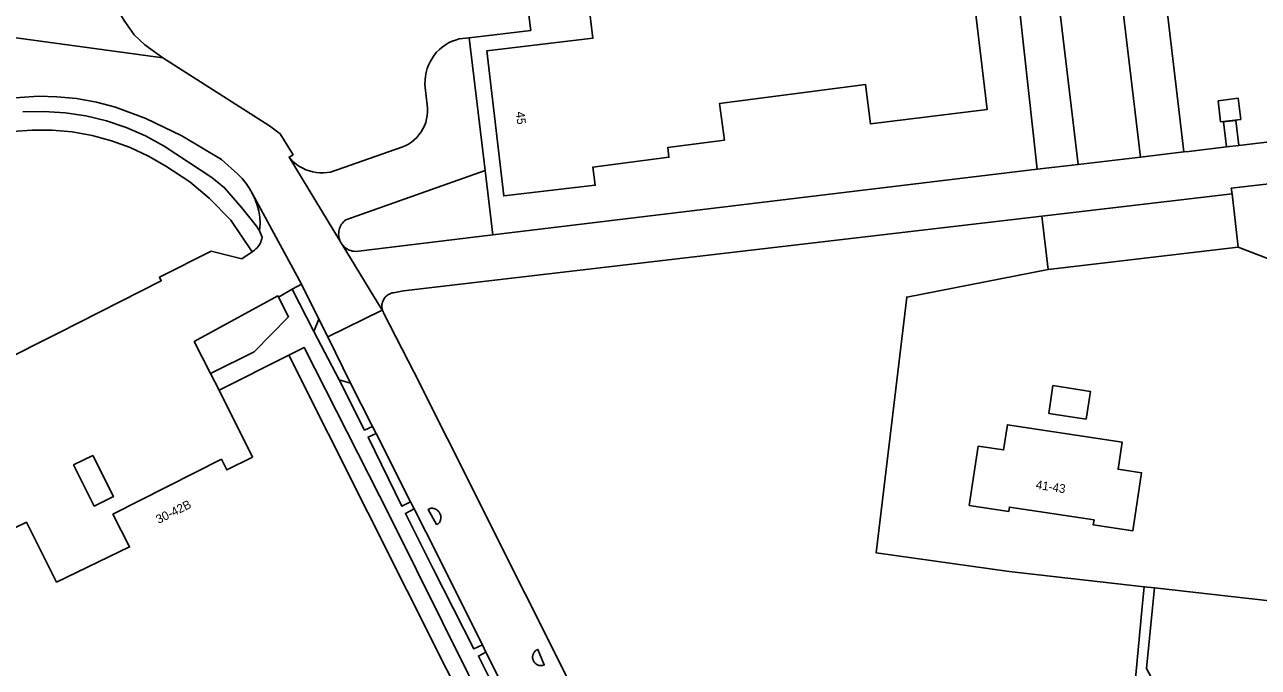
# Model space of a CAD drawing. Extents: x 158132 to 159664, y 385256 to 387218.
# Drawn here: x 159028.7 to 159170.4, y 386531.1 to 386604.9 of the extents above; entities that cross this region are included whole.
import ezdxf

# ---------------------------------------------------------------- set-up
doc = ezdxf.new("R2010")
doc.units = 0
for name, color, linetype in [('IMGEO_Berm_groen', 7, 'Continuous'), ('IMGEO_Erf', 7, 'Continuous'), ('IMGEO_Groenvoorziening', 7, 'Continuous'), ('IMGEO_Loofbos', 7, 'Continuous'), ('IMGEO_Pand', 7, 'Continuous'), ('IMGEO_Pand_nummerreeks', 7, 'Continuous'), ('IMGEO_Parkeervlak_gesloten', 7, 'Continuous'), ('IMGEO_Parkeervlak_open', 7, 'Continuous'), ('IMGEO_Rijbaan_lokaal_gesloten', 7, 'Continuous'), ('IMGEO_Rijbaan_lokaal_open', 7, 'Continuous'), ('IMGEO_Verkeerseiland_gesloten', 7, 'Continuous'), ('IMGEO_Voetpad_open', 7, 'Continuous')]:
    doc.layers.add(name, color=color, linetype=linetype)

msp = doc.modelspace()

# ---------------------------------------------------------------- linework, layer by layer
at = {"layer": 'IMGEO_Berm_groen'}
msp.add_lwpolyline([(159028.48, 386594.92), (159030.9, 386594.98), (159033.32, 386594.83), (159035.71, 386594.47), (159038.07, 386593.9), (159040.36, 386593.13), (159042.58, 386592.16), (159044.71, 386591), (159050.19, 386587.39), (159051.65, 386586.21), (159053.63, 386583.89), (159055.32, 386581.82), (159055.67, 386581.25), (159055.74, 386582.11), (159055.68, 386582.82), (159055.57, 386583.51), (159055.39, 386584.2), (159055.15, 386584.87), (159054.86, 386585.51), (159054.52, 386586.13), (159054.12, 386586.72), (159053.68, 386587.27), (159053.19, 386587.78), (159051.31, 386589.44), (159046.74, 386592.18), (159042.61, 386594.15), (159039.13, 386595.45), (159036.92, 386596.06), (159034.65, 386596.46), (159032.37, 386596.65), (159030.29, 386596.74), (159024.92, 386596.33)], dxfattribs=at)
for points in [[(159060.48, 386575.13), (159059.42, 386574.58), (159061.91, 386569.71), (159062.46, 386571.11)], [(159059, 386571.4), (159057.85, 386573.66), (159057.77, 386573.8), (159048.17, 386568.54), (159050.03, 386564.89), (159055.03, 386567.36)], [(159066.12, 386563.76), (159064.8, 386564.17), (159067.73, 386558.38), (159068.64, 386558.78)], [(159069.05, 386557.98), (159068.14, 386557.58), (159072.03, 386549.64), (159073.01, 386550.16)], [(159074.81, 386546.61), (159073.43, 386549.34), (159072.43, 386548.81), (159075.6, 386542.45), (159080.3, 386533.25), (159081.26, 386533.72)], [(159083.47, 386529.31), (159081.68, 386532.89), (159080.81, 386532.42), (159089.95, 386514.21), (159090.83, 386514.64)]]:
    msp.add_lwpolyline(points, close=True, dxfattribs=at)
at = {"layer": 'IMGEO_Erf'}
for points in [[(159168.09, 386579.39), (159146.27, 386576.84), (159130.01, 386573.65), (159126.49, 386544.29), (159141.76, 386542.14), (159157.3, 386540.4), (159158.49, 386540.26), (159174.04, 386538.52), (159176.11, 386538.29), (159179.55, 386575)], [(159151.11, 386562.83), (159150.62, 386559.65), (159146.32, 386560.3), (159146.81, 386563.49)], [(159155.97, 386546.81), (159151.44, 386547.5), (159151.53, 386548.07), (159141.81, 386549.55), (159141.73, 386549.04), (159137.19, 386549.73), (159138.23, 386556.55), (159141.13, 386556.11), (159141.57, 386559), (159154.77, 386556.99), (159154.3, 386553.89), (159156.99, 386553.48)]]:
    msp.add_lwpolyline(points, close=True, dxfattribs=at)
at = {"layer": 'IMGEO_Groenvoorziening'}
for points in [[(159157.64, 386625.98), (159161.85, 386590.32), (159162.42, 386590.39), (159166.74, 386590.91), (159166.39, 386593.77), (159167.8, 386593.95), (159168.15, 386591.07), (159175.18, 386591.91)], [(159040.19, 386605.29), (159041.26, 386603.78), (159042.49, 386602.63), (159044.57, 386601.15), (159056.81, 386593.34), (159058.02, 386592.39), (159059.51, 386590.01), (159059.05, 386589.73), (159059.32, 386589.42), (159059.62, 386589.14), (159059.93, 386588.88), (159060.27, 386588.65), (159060.63, 386588.45), (159061, 386588.28), (159061.39, 386588.14), (159061.79, 386588.03), (159062.19, 386587.96), (159062.6, 386587.92), (159063.01, 386587.92), (159063.42, 386587.95), (159063.82, 386588.02), (159072.03, 386590.86), (159072.41, 386591.02), (159072.77, 386591.22), (159073.11, 386591.44), (159073.42, 386591.7), (159073.72, 386591.98), (159073.98, 386592.29), (159074.22, 386592.62), (159074.43, 386592.97), (159074.61, 386593.34), (159074.75, 386593.72), (159074.85, 386594.11), (159074.92, 386594.51), (159074.96, 386594.92), (159074.96, 386595.33), (159074.92, 386595.73), (159074.7, 386597.72), (159074.67, 386598.16), (159074.68, 386598.6), (159074.72, 386599.03), (159074.8, 386599.46), (159074.92, 386599.89), (159075.07, 386600.3), (159075.26, 386600.69), (159075.48, 386601.07), (159075.73, 386601.43), (159076.01, 386601.77), (159076.32, 386602.08), (159076.65, 386602.36), (159077.01, 386602.62), (159077.38, 386602.84), (159077.78, 386603.03), (159078.19, 386603.18), (159078.61, 386603.31), (159079.74, 386603.44), (159086.82, 386604.28), (159086.76, 386604.82), (159086.16, 386609.81)], [(159025.65, 386566.07), (159032.6, 386569.55), (159044.38, 386575.53), (159044.19, 386575.96), (159050.09, 386578.94), (159053.63, 386578.06), (159054.82, 386578.85), (159052.35, 386582.48), (159049.86, 386585.02), (159047.64, 386586.89), (159044.91, 386588.71), (159042.91, 386589.86), (159040.82, 386590.83), (159038.65, 386591.62), (159036.42, 386592.22), (159034.14, 386592.62), (159031.85, 386592.83), (159029.54, 386592.84), (159027.24, 386592.66)], [(159146.27, 386576.84), (159145.55, 386582.95), (159072.19, 386574.38), (159071.06, 386574.16), (159070.92, 386574.14), (159070.79, 386574.1), (159070.66, 386574.05), (159070.54, 386573.99), (159070.42, 386573.92), (159070.31, 386573.84), (159070.21, 386573.75), (159070.11, 386573.65), (159070.03, 386573.55), (159069.95, 386573.43), (159069.89, 386573.31), (159069.83, 386573.19), (159069.79, 386573.06), (159069.75, 386572.93), (159069.73, 386572.79), (159069.72, 386572.65), (159069.73, 386572.52), (159069.74, 386572.38), (159069.77, 386572.25), (159069.8, 386572.11), (159069.86, 386571.99), (159069.92, 386571.86), (159073.41, 386564.98), (159077.26, 386557.36), (159086.18, 386539.58), (159101.17, 386509.73)], [(159148.23, 386529.21), (159156.1, 386528.28), (159156.17, 386528.64), (159157.04, 386538.09), (159157.3, 386540.4), (159141.76, 386542.14), (159126.49, 386544.29), (159130.01, 386573.65), (159146.27, 386576.84)]]:
    msp.add_lwpolyline(points, dxfattribs=at)
for points in [[(159168.1, 386596.5), (159168.38, 386594.06), (159166.07, 386593.77), (159165.79, 386596.21)], [(159081.58, 386588.19), (159065.57, 386582.53), (159065.44, 386582.42), (159065.31, 386582.3), (159065.19, 386582.16), (159065.09, 386582.02), (159065, 386581.87), (159064.92, 386581.71), (159064.86, 386581.55), (159064.81, 386581.38), (159064.77, 386581.21), (159064.76, 386581.03), (159064.75, 386580.85), (159064.77, 386580.68), (159064.79, 386580.51), (159064.84, 386580.33), (159064.89, 386580.17), (159064.97, 386580.01), (159065.05, 386579.85), (159065.15, 386579.71), (159065.26, 386579.57), (159065.39, 386579.44), (159065.52, 386579.33), (159065.66, 386579.23), (159065.82, 386579.14), (159065.97, 386579.06), (159066.14, 386579), (159066.31, 386578.95), (159066.48, 386578.92), (159066.71, 386578.91), (159082.47, 386580.81)], [(159070.67, 386548.43), (159060.8, 386567.86), (159059.03, 386566.97), (159086.21, 386512.87), (159088, 386513.77), (159082.68, 386524.24)]]:
    msp.add_lwpolyline(points, close=True, dxfattribs=at)
at = {"layer": 'IMGEO_Loofbos'}
msp.add_lwpolyline([(159250.17, 386500), (159194.12, 386589.79), (159192.73, 386592.19), (159192.21, 386592.03), (159176.64, 386587.24), (159167.3, 386586.15), (159167.38, 386585.5), (159168.09, 386579.39), (159179.55, 386575), (159176.11, 386538.29), (159174.04, 386538.52), (159158.49, 386540.26), (159158.23, 386537.96), (159157.57, 386530.99)], dxfattribs=at)
at = {"layer": 'IMGEO_Pand'}
for points in [[(159083.72, 386585.27), (159094.23, 386586.5), (159093.96, 386588.58), (159102.69, 386589.71), (159102.55, 386590.83), (159109.06, 386591.67), (159108.52, 386595.89), (159125.29, 386598.06), (159125.84, 386593.54), (159139.27, 386595.21), (159136.34, 386619.6), (159122.39, 386617.92), (159122.93, 386613.74), (159106.38, 386611.59), (159106.64, 386609.58), (159093.42, 386607.87), (159093.96, 386603.38), (159081.77, 386601.93)], [(159168.1, 386596.5), (159165.79, 386596.21), (159166.07, 386593.77), (159168.38, 386594.06)], [(159150.62, 386559.65), (159151.11, 386562.83), (159146.81, 386563.49), (159146.32, 386560.3)], [(159155.97, 386546.81), (159156.99, 386553.48), (159154.3, 386553.89), (159154.77, 386556.99), (159141.57, 386559), (159141.13, 386556.11), (159138.23, 386556.55), (159137.19, 386549.73), (159141.73, 386549.04), (159141.81, 386549.55), (159151.53, 386548.07), (159151.44, 386547.5)]]:
    msp.add_lwpolyline(points, close=True, dxfattribs=at)
msp.add_lwpolyline([(159086.21, 386512.87), (159059.03, 386566.97), (159051.01, 386562.95), (159054.86, 386555.28), (159051.91, 386553.8), (159051.29, 386555.03), (159038.83, 386548.71), (159040.73, 386544.97), (159032.36, 386540.93), (159028.89, 386547.79), (159026.2, 386546.5), (159024.99, 386548.9), (159009.85, 386541.29), (159011.17, 386538.61), (159005.81, 386535.92), (159008.38, 386530.8)], dxfattribs=at)
at = {"layer": 'IMGEO_Parkeervlak_gesloten'}
msp.add_lwpolyline([(159034.3, 386554.39), (159036.68, 386549.66), (159038.88, 386550.74), (159036.5, 386555.47)], close=True, dxfattribs=at)
at = {"layer": 'IMGEO_Parkeervlak_open'}
for points in [[(159157.64, 386625.98), (159152.62, 386625.38), (159156.87, 386589.74), (159161.85, 386590.32)], [(159145.47, 386624.52), (159141.03, 386623.99), (159141.5, 386620.01), (159144.99, 386588.33), (159149.71, 386588.89)], [(159063.5, 386569.1), (159062.46, 386571.11), (159061.91, 386569.71), (159064.8, 386564.17), (159066.12, 386563.76)], [(159034.3, 386554.39), (159036.5, 386555.47), (159038.88, 386550.74), (159036.68, 386549.66)]]:
    msp.add_lwpolyline(points, close=True, dxfattribs=at)
for points in [[(159051.01, 386562.95), (159050.03, 386564.89), (159048.17, 386568.54), (159057.77, 386573.8), (159057.85, 386573.66), (159059.42, 386574.58), (159060.48, 386575.13), (159054.86, 386585.51), (159055.15, 386584.87), (159055.39, 386584.2), (159055.57, 386583.51), (159055.68, 386582.82), (159055.74, 386582.11), (159055.67, 386581.25), (159055.96, 386580.55), (159055.93, 386580.35), (159055.87, 386580.16), (159055.8, 386579.98), (159055.72, 386579.8), (159055.62, 386579.63), (159055.51, 386579.47), (159055.38, 386579.32), (159055.24, 386579.18), (159055.09, 386579.05), (159054.93, 386578.93), (159054.82, 386578.85), (159053.63, 386578.06), (159050.09, 386578.94), (159044.19, 386575.96), (159044.38, 386575.53), (159032.6, 386569.55), (159025.65, 386566.07)], [(159008.94, 386543.13), (159009.85, 386541.29), (159024.99, 386548.9), (159026.2, 386546.5), (159028.89, 386547.79), (159032.36, 386540.93), (159040.73, 386544.97), (159038.83, 386548.71), (159051.29, 386555.03), (159051.91, 386553.8), (159054.86, 386555.28), (159051.01, 386562.95)]]:
    msp.add_lwpolyline(points, dxfattribs=at)
at = {"layer": 'IMGEO_Rijbaan_lokaal_gesloten'}
for points in [[(159023.71, 386603.96), (159044.57, 386601.15), (159042.49, 386602.63), (159041.26, 386603.78), (159040.19, 386605.29), (159039.36, 386606.65), (159038.66, 386608.33), (159037.97, 386610.71)], [(159024.92, 386596.33), (159030.29, 386596.74), (159032.37, 386596.65), (159034.65, 386596.46), (159036.92, 386596.06), (159039.13, 386595.45), (159042.61, 386594.15), (159046.74, 386592.18), (159051.31, 386589.44), (159053.19, 386587.78), (159053.68, 386587.27), (159054.12, 386586.72), (159054.52, 386586.13), (159054.86, 386585.51), (159060.48, 386575.13), (159062.46, 386571.11), (159063.5, 386569.1), (159069.76, 386572.15), (159065.15, 386579.71), (159065.05, 386579.85), (159064.97, 386580.01), (159059.05, 386589.73), (159059.51, 386590.01), (159058.02, 386592.39), (159056.81, 386593.34), (159044.57, 386601.15), (159023.71, 386603.96)]]:
    msp.add_lwpolyline(points, dxfattribs=at)
at = {"layer": 'IMGEO_Rijbaan_lokaal_open'}
for points in [[(159152.62, 386625.38), (159145.47, 386624.52), (159149.71, 386588.89), (159156.87, 386589.74)], [(159167.38, 386585.5), (159145.55, 386582.95), (159146.27, 386576.84), (159168.09, 386579.39)], [(159075.03, 386549.25), (159075.27, 386549.38), (159075.36, 386549.4), (159075.45, 386549.4), (159075.54, 386549.4), (159075.63, 386549.39), (159075.71, 386549.37), (159075.8, 386549.34), (159075.88, 386549.31), (159075.96, 386549.27), (159076.04, 386549.22), (159076.11, 386549.16), (159076.18, 386549.1), (159076.24, 386549.04), (159076.3, 386548.96), (159076.35, 386548.89), (159076.39, 386548.81), (159076.43, 386548.73), (159076.46, 386548.64), (159076.48, 386548.55), (159076.49, 386548.46), (159076.49, 386548.37), (159076.49, 386548.28), (159076.48, 386548.19), (159076.46, 386548.1), (159076.44, 386548.02), (159076.4, 386547.93), (159076.36, 386547.85), (159076.32, 386547.77), (159076.26, 386547.7), (159076.2, 386547.63), (159076.01, 386547.55)], [(159088.1, 386531.33), (159088.02, 386531.33), (159087.93, 386531.34), (159087.85, 386531.35), (159087.76, 386531.36), (159087.68, 386531.39), (159087.61, 386531.42), (159087.53, 386531.46), (159087.46, 386531.51), (159087.39, 386531.56), (159087.33, 386531.61), (159087.27, 386531.68), (159087.22, 386531.74), (159087.17, 386531.81), (159087.13, 386531.89), (159087.1, 386531.97), (159087.07, 386532.05), (159087.05, 386532.13), (159087.04, 386532.21), (159087.04, 386532.3), (159087.04, 386532.38), (159087.05, 386532.47), (159087.06, 386532.55), (159087.09, 386532.63), (159087.12, 386532.71), (159087.15, 386532.78), (159087.2, 386532.86), (159087.25, 386532.92), (159087.3, 386532.99), (159087.36, 386533.05), (159087.43, 386533.1), (159087.64, 386533.19), (159088.38, 386531.41), (159088.18, 386531.35)]]:
    msp.add_lwpolyline(points, close=True, dxfattribs=at)
for points in [[(159175.18, 386591.91), (159168.15, 386591.07), (159166.74, 386590.91), (159162.42, 386590.39), (159161.85, 386590.32), (159156.87, 386589.74), (159149.71, 386588.89), (159144.99, 386588.33), (159082.47, 386580.81), (159066.71, 386578.91), (159066.48, 386578.92), (159066.31, 386578.95), (159066.14, 386579), (159065.97, 386579.06), (159065.82, 386579.14), (159065.66, 386579.23), (159065.52, 386579.33), (159065.39, 386579.44), (159065.26, 386579.57), (159065.15, 386579.71), (159069.76, 386572.15), (159069.86, 386571.99), (159069.8, 386572.11), (159069.77, 386572.25), (159069.74, 386572.38), (159069.73, 386572.52), (159069.72, 386572.65), (159069.73, 386572.79), (159069.75, 386572.93), (159069.79, 386573.06), (159069.83, 386573.19), (159069.89, 386573.31), (159069.95, 386573.43), (159070.03, 386573.55), (159070.11, 386573.65), (159070.21, 386573.75), (159070.31, 386573.84), (159070.42, 386573.92), (159070.54, 386573.99), (159070.66, 386574.05), (159070.79, 386574.1), (159070.92, 386574.14), (159071.06, 386574.16), (159072.19, 386574.38), (159145.55, 386582.95), (159167.38, 386585.5), (159167.3, 386586.15), (159176.64, 386587.24)], [(159101.17, 386509.73), (159086.18, 386539.58), (159077.26, 386557.36), (159073.41, 386564.98), (159069.92, 386571.86), (159069.86, 386571.99), (159069.76, 386572.15), (159063.5, 386569.1), (159066.12, 386563.76), (159068.64, 386558.78), (159069.05, 386557.98), (159073.01, 386550.16), (159073.43, 386549.34), (159074.81, 386546.61), (159081.26, 386533.72), (159081.68, 386532.89), (159083.47, 386529.31)]]:
    msp.add_lwpolyline(points, dxfattribs=at)
at = {"layer": 'IMGEO_Verkeerseiland_gesloten'}
for points in [[(159075.27, 386549.38), (159075.03, 386549.25), (159076.01, 386547.55), (159076.2, 386547.63), (159076.26, 386547.7), (159076.32, 386547.77), (159076.36, 386547.85), (159076.4, 386547.93), (159076.44, 386548.02), (159076.46, 386548.1), (159076.48, 386548.19), (159076.49, 386548.28), (159076.49, 386548.37), (159076.49, 386548.46), (159076.48, 386548.55), (159076.46, 386548.64), (159076.43, 386548.73), (159076.39, 386548.81), (159076.35, 386548.89), (159076.3, 386548.96), (159076.24, 386549.04), (159076.18, 386549.1), (159076.11, 386549.16), (159076.04, 386549.22), (159075.96, 386549.27), (159075.88, 386549.31), (159075.8, 386549.34), (159075.71, 386549.37), (159075.63, 386549.39), (159075.54, 386549.4), (159075.45, 386549.4), (159075.36, 386549.4)], [(159088.18, 386531.35), (159088.38, 386531.41), (159087.64, 386533.19), (159087.43, 386533.1), (159087.36, 386533.05), (159087.3, 386532.99), (159087.25, 386532.92), (159087.2, 386532.86), (159087.15, 386532.78), (159087.12, 386532.71), (159087.09, 386532.63), (159087.06, 386532.55), (159087.05, 386532.47), (159087.04, 386532.38), (159087.04, 386532.3), (159087.04, 386532.21), (159087.05, 386532.13), (159087.07, 386532.05), (159087.1, 386531.97), (159087.13, 386531.89), (159087.17, 386531.81), (159087.22, 386531.74), (159087.27, 386531.68), (159087.33, 386531.61), (159087.39, 386531.56), (159087.46, 386531.51), (159087.53, 386531.46), (159087.61, 386531.42), (159087.68, 386531.39), (159087.76, 386531.36), (159087.85, 386531.35), (159087.93, 386531.34), (159088.02, 386531.33), (159088.1, 386531.33)]]:
    msp.add_lwpolyline(points, close=True, dxfattribs=at)
at = {"layer": 'IMGEO_Voetpad_open'}
for points in [[(159138.19, 386623.65), (159121.25, 386621.63), (159120.92, 386624.39), (159105.07, 386622.5), (159105.83, 386616.14), (159094.16, 386614.74), (159092.39, 386614.53), (159092.86, 386610.61), (159086.16, 386609.81), (159086.76, 386604.82), (159086.82, 386604.28), (159079.74, 386603.44), (159081.58, 386588.19), (159082.47, 386580.81), (159144.99, 386588.33), (159141.5, 386620.01), (159138.66, 386619.69)], [(159106.64, 386609.58), (159106.38, 386611.59), (159122.93, 386613.74), (159122.39, 386617.92), (159136.34, 386619.6), (159139.27, 386595.21), (159125.84, 386593.54), (159125.29, 386598.06), (159108.52, 386595.89), (159109.06, 386591.67), (159102.55, 386590.83), (159102.69, 386589.71), (159093.96, 386588.58), (159094.23, 386586.5), (159083.72, 386585.27), (159081.77, 386601.93), (159093.96, 386603.38), (159093.42, 386607.87)], [(159081.58, 386588.19), (159079.74, 386603.44), (159078.61, 386603.31), (159078.19, 386603.18), (159077.78, 386603.03), (159077.38, 386602.84), (159077.01, 386602.62), (159076.65, 386602.36), (159076.32, 386602.08), (159076.01, 386601.77), (159075.73, 386601.43), (159075.48, 386601.07), (159075.26, 386600.69), (159075.07, 386600.3), (159074.92, 386599.89), (159074.8, 386599.46), (159074.72, 386599.03), (159074.68, 386598.6), (159074.67, 386598.16), (159074.7, 386597.72), (159074.92, 386595.73), (159074.96, 386595.33), (159074.96, 386594.92), (159074.92, 386594.51), (159074.85, 386594.11), (159074.75, 386593.72), (159074.61, 386593.34), (159074.43, 386592.97), (159074.22, 386592.62), (159073.98, 386592.29), (159073.72, 386591.98), (159073.42, 386591.7), (159073.11, 386591.44), (159072.77, 386591.22), (159072.41, 386591.02), (159072.03, 386590.86), (159063.82, 386588.02), (159063.42, 386587.95), (159063.01, 386587.92), (159062.6, 386587.92), (159062.19, 386587.96), (159061.79, 386588.03), (159061.39, 386588.14), (159061, 386588.28), (159060.63, 386588.45), (159060.27, 386588.65), (159059.93, 386588.88), (159059.62, 386589.14), (159059.32, 386589.42), (159059.05, 386589.73), (159064.97, 386580.01), (159064.89, 386580.17), (159064.84, 386580.33), (159064.79, 386580.51), (159064.77, 386580.68), (159064.75, 386580.85), (159064.76, 386581.03), (159064.77, 386581.21), (159064.81, 386581.38), (159064.86, 386581.55), (159064.92, 386581.71), (159065, 386581.87), (159065.09, 386582.02), (159065.19, 386582.16), (159065.31, 386582.3), (159065.44, 386582.42), (159065.57, 386582.53)], [(159166.74, 386590.91), (159168.15, 386591.07), (159167.8, 386593.95), (159166.39, 386593.77)], [(159157.57, 386530.99), (159158.23, 386537.96), (159158.49, 386540.26), (159157.3, 386540.4), (159157.04, 386538.09), (159156.17, 386528.64), (159156.1, 386528.28), (159156.35, 386528.25), (159157.52, 386528.08), (159158.92, 386527.72), (159159.49, 386527.35)]]:
    msp.add_lwpolyline(points, close=True, dxfattribs=at)
for points in [[(159027.24, 386592.66), (159029.54, 386592.84), (159031.85, 386592.83), (159034.14, 386592.62), (159036.42, 386592.22), (159038.65, 386591.62), (159040.82, 386590.83), (159042.91, 386589.86), (159044.91, 386588.71), (159047.64, 386586.89), (159049.86, 386585.02), (159052.35, 386582.48), (159054.82, 386578.85), (159054.93, 386578.93), (159055.09, 386579.05), (159055.24, 386579.18), (159055.38, 386579.32), (159055.51, 386579.47), (159055.62, 386579.63), (159055.72, 386579.8), (159055.8, 386579.98), (159055.87, 386580.16), (159055.93, 386580.35), (159055.96, 386580.55), (159055.67, 386581.25), (159055.32, 386581.82), (159053.63, 386583.89), (159051.65, 386586.21), (159050.19, 386587.39), (159044.71, 386591), (159042.58, 386592.16), (159040.36, 386593.13), (159038.07, 386593.9), (159035.71, 386594.47), (159033.32, 386594.83), (159030.9, 386594.98), (159028.48, 386594.92)], [(159089.95, 386514.21), (159080.81, 386532.42), (159081.68, 386532.89), (159081.26, 386533.72), (159080.3, 386533.25), (159075.6, 386542.45), (159072.43, 386548.81), (159073.43, 386549.34), (159073.01, 386550.16), (159072.03, 386549.64), (159068.14, 386557.58), (159069.05, 386557.98), (159068.64, 386558.78), (159067.73, 386558.38), (159064.8, 386564.17), (159061.91, 386569.71), (159059.42, 386574.58), (159057.85, 386573.66), (159059, 386571.4), (159055.03, 386567.36), (159050.03, 386564.89), (159051.01, 386562.95), (159059.03, 386566.97), (159060.8, 386567.86), (159070.67, 386548.43), (159082.68, 386524.24)]]:
    msp.add_lwpolyline(points, dxfattribs=at)

# ---------------------------------------------------------------- texts
at = {"layer": 'IMGEO_Pand_nummerreeks'}
for s, rotation, p in [('45', 276.2452, (159085.12, 386594.91)), ('41-43', 351.1791, (159144.79, 386551.65)), ('30-42B', 26.4477, (159044.07, 386547.6))]:
    msp.add_text(s, height=1, rotation=rotation, dxfattribs=at).set_placement(p)

doc.saveas('drawing.dxf')
